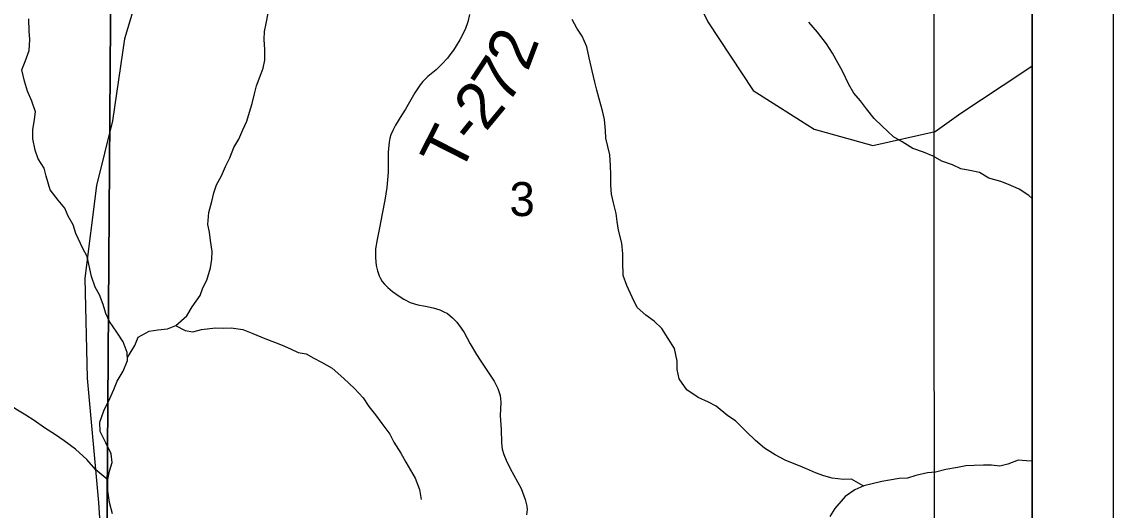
# Model space of a CAD drawing. Extents: x 0 to 34, y 0 to 22.
# Drawn here: x 7.655 to 9, y 17.724 to 18.326 of the extents above; entities that cross this region are included whole.
import ezdxf

# ---------------------------------------------------------------- set-up
doc = ezdxf.new("R2010")
doc.units = 0
for name, color, linetype in [('Default', 7, 'Continuous'), ('GM_X_Minor_River', 7, 'Continuous'), ('GM_X_Rail_Line', 7, 'Continuous'), ('GM_X_Section', 7, 'Continuous'), ('GM_X_Section_Text', 7, 'Continuous'), ('GM_X_Township_Road', 7, 'Continuous'), ('GM_X_Township_Road_Text', 7, 'Continuous'), ('SH_Cut_Line', 7, 'Continuous'), ('SH_Data', 7, 'Continuous')]:
    doc.layers.add(name, color=color, linetype=linetype)

msp = doc.modelspace()

# ---------------------------------------------------------------- linework, layer by layer
at = {"layer": 'Default'}
msp.add_lwpolyline([(8.9, 17.6215), (8.9, 18.6179), (8.8175, 18.6179), (8.7788, 18.6182), (8.7796, 17.6215)], close=True, dxfattribs=at)
at = {"layer": 'GM_X_Minor_River'}
for points in [[(7.7518, 17.8211), (7.7513, 17.8329), (7.7562, 17.8469), (7.7637, 17.8618), (7.7685, 17.8732), (7.7726, 17.8831), (7.7801, 17.8956), (7.7857, 17.9086), (7.7853, 17.9188), (7.7803, 17.9317), (7.7722, 17.9438), (7.7634, 17.957), (7.7588, 17.9668), (7.7557, 17.9778), (7.751, 17.9895), (7.7457, 17.9993), (7.741, 18.0122), (7.7359, 18.0368), (7.7305, 18.0467), (7.7217, 18.0652), (7.7186, 18.0758), (7.7124, 18.0867), (7.7082, 18.0966), (7.7002, 18.1064), (7.6902, 18.1192), (7.6855, 18.1359), (7.6828, 18.1457), (7.6755, 18.1574), (7.6717, 18.1677), (7.6689, 18.182), (7.6688, 18.193), (7.671, 18.2056), (7.6721, 18.2151), (7.6675, 18.2283), (7.6624, 18.2404), (7.6586, 18.2529), (7.6554, 18.2669), (7.6595, 18.2772), (7.6644, 18.2909), (7.6651, 18.3042), (7.6642, 18.3144), (7.6638, 18.3296)], [(7.7856, 17.9123), (7.7947, 17.9272), (7.7988, 17.9375), (7.8121, 17.9448), (7.8227, 17.9464), (7.8349, 17.9476), (7.8451, 17.9518), (7.8587, 17.9637), (7.8654, 17.9747), (7.8752, 17.9888), (7.8782, 17.9983), (7.8834, 18.0078), (7.8879, 18.023), (7.8893, 18.0337), (7.89, 18.0431), (7.8877, 18.0568), (7.8865, 18.067), (7.8845, 18.0765), (7.8859, 18.0913), (7.8893, 18.1046), (7.8918, 18.1152), (7.8952, 18.1251), (7.9012, 18.1361), (7.9061, 18.1476), (7.9117, 18.1586), (7.9165, 18.1711), (7.9225, 18.1814), (7.9278, 18.1928), (7.9326, 18.2035), (7.936, 18.2149), (7.939, 18.2255), (7.9419, 18.2373), (7.9445, 18.2472), (7.949, 18.259), (7.9527, 18.2689), (7.9549, 18.2787), (7.9548, 18.292), (7.954, 18.3041), (7.9543, 18.314), (7.9562, 18.3239), (7.9587, 18.3368)], [(8.6921, 17.7542), (8.6775, 17.7627), (8.6676, 17.7622), (8.6539, 17.7637), (8.6433, 17.7666), (8.6334, 17.7703), (8.6223, 17.7752), (8.6121, 17.7793), (8.5968, 17.7857), (8.5835, 17.7924), (8.5702, 17.8007), (8.5591, 17.8101), (8.548, 17.8214), (8.5346, 17.8346), (8.5251, 17.8406), (8.511, 17.8526), (8.5014, 17.8575), (8.4885, 17.8631), (8.4748, 17.8725), (8.4652, 17.8861), (8.4628, 17.8978), (8.4628, 17.9081), (8.4596, 17.9236), (8.4519, 17.936), (8.4439, 17.9481), (8.4343, 17.9572), (8.424, 17.9647), (8.4133, 17.9741), (8.4072, 17.9866), (8.4006, 18.001), (8.3964, 18.0134), (8.3959, 18.0305), (8.3958, 18.04), (8.3946, 18.0533), (8.3907, 18.0692), (8.3887, 18.0801), (8.3875, 18.09), (8.3844, 18.1029), (8.3817, 18.1135), (8.3812, 18.1249), (8.3811, 18.1381), (8.3807, 18.1487), (8.3798, 18.162), (8.3775, 18.1726), (8.3748, 18.1828), (8.3743, 18.1923), (8.3731, 18.2056), (8.3707, 18.2162), (8.3665, 18.231), (8.3637, 18.2419), (8.3614, 18.2518), (8.3579, 18.2658), (8.3544, 18.2817), (8.3516, 18.2953), (8.3458, 18.3082), (8.3393, 18.3184), (8.3335, 18.329)], [(8.9, 18.1085), (8.8962, 18.1119), (8.884, 18.1198), (8.871, 18.1258), (8.8615, 18.1291), (8.847, 18.1336), (8.8352, 18.1403), (8.8234, 18.1429), (8.8124, 18.1451), (8.8021, 18.15), (8.7888, 18.1544), (8.7781, 18.1604), (8.7663, 18.1653), (8.753, 18.1701), (8.74, 18.178), (8.7294, 18.1844), (8.7152, 18.1976), (8.7057, 18.207), (8.6961, 18.2187), (8.6885, 18.2285), (8.6804, 18.2383), (8.6743, 18.2489), (8.6666, 18.2651), (8.6608, 18.2754), (8.6543, 18.2874), (8.6466, 18.2988), (8.6355, 18.3131), (8.6252, 18.3256)], [(7.8447, 17.9517), (7.8565, 17.9458), (7.866, 17.944), (7.8766, 17.9471), (7.8941, 17.9491), (7.9039, 17.9488), (7.9134, 17.9489), (7.9275, 17.947), (7.9401, 17.9422), (7.9549, 17.9358), (7.9667, 17.9314), (7.9762, 17.9276), (7.9865, 17.9232), (7.996, 17.9187), (8.0055, 17.9168), (8.0151, 17.9116), (8.0246, 17.9067), (8.0375, 17.8992), (8.0521, 17.8864), (8.0651, 17.8744), (8.0758, 17.8627), (8.083, 17.8521), (8.0911, 17.8419), (8.0987, 17.8313), (8.1087, 17.8181), (8.1137, 17.8083), (8.1222, 17.7947), (8.1283, 17.7837), (8.1341, 17.7735), (8.1398, 17.7637), (8.1452, 17.7497), (8.1472, 17.7376)], [(7.7613, 17.7616), (7.7464, 17.7741), (7.7353, 17.7869), (7.7215, 17.7997), (7.7074, 17.8098), (7.6967, 17.817), (7.6834, 17.826), (7.6704, 17.835), (7.6601, 17.8414), (7.6502, 17.8474), (7.638, 17.8553), (7.6266, 17.8639), (7.617, 17.8699), (7.6064, 17.8763), (7.5965, 17.8808), (7.5854, 17.8872), (7.5759, 17.8913), (7.5648, 17.8969), (7.5519, 17.9048), (7.5404, 17.9123), (7.5305, 17.9179), (7.5199, 17.922), (7.5069, 17.9291)], [(7.7669, 17.7199), (7.7634, 17.734), (7.7614, 17.748), (7.7613, 17.762), (7.7635, 17.7723), (7.7665, 17.7829), (7.7652, 17.7939), (7.7587, 17.8075), (7.7518, 17.8211)], [(8.9, 17.7846), (8.8934, 17.7853), (8.8831, 17.786), (8.8702, 17.781), (8.8604, 17.7787), (8.8501, 17.7797), (8.8403, 17.78), (8.8289, 17.7792), (8.8186, 17.7788), (8.808, 17.7768), (8.794, 17.7744), (8.7811, 17.7713), (8.7712, 17.7705), (8.7568, 17.767), (8.7466, 17.7639), (8.7363, 17.7634), (8.7246, 17.7615), (8.7151, 17.7595), (8.703, 17.7568), (8.6927, 17.7544), (8.6817, 17.7494), (8.6696, 17.7414), (8.6572, 17.7265), (8.6508, 17.7166)]]:
    msp.add_lwpolyline(points, dxfattribs=at)
at = {"layer": 'GM_X_Rail_Line'}
msp.add_lwpolyline([(5.9824, 16.6436), (7.149, 16.6283), (7.6814, 16.6224), (7.7376, 16.622), (7.7377, 16.1663), (7.7446, 16.1373), (7.7538, 15.9954), (7.756, 15.9342), (7.7526, 15.9181), (7.7434, 15.892), (7.7355, 15.6105), (7.8392, 15.6096), (8.369, 15.6108), (8.7708, 15.6025), (8.77, 15.1835), (8.767, 14.6265), (8.9, 14.624), (8.9, 20.9)], dxfattribs=at)
at = {"layer": 'GM_X_Section'}
for points in [[(6.7712, 18.6214), (6.7897, 18.6209), (7.7667, 18.6191), (7.7595, 17.6205), (6.7568, 17.6224)], [(7.7667, 18.6191), (7.7955, 18.6195), (8.7788, 18.6182), (8.7796, 17.6215), (7.7595, 17.6205)]]:
    msp.add_lwpolyline(points, close=True, dxfattribs=at)
at = {"layer": 'GM_X_Township_Road'}
for points in [[(7.8117, 18.4807), (7.8122, 18.4788), (7.8194, 18.4479), (7.8179, 18.4023), (7.7996, 18.3642), (7.7818, 18.3052), (7.7671, 18.2041), (7.7472, 18.1242), (7.7329, 18.0102), (7.7357, 17.8869), (7.7498, 17.734), (7.755, 17.6517), (7.7598, 17.5188), (7.7622, 17.4448)], [(8.4568, 18.4172), (8.5007, 18.326), (8.5563, 18.2414), (8.6314, 18.1938), (8.704, 18.1738), (8.7805, 18.1908), (8.8121, 18.2134), (8.89, 18.2647), (8.9, 18.2719)], [(8.2071, 18.335), (8.2048, 18.3259), (8.2017, 18.3165), (8.1951, 18.304), (8.1905, 18.2964), (8.1871, 18.2912), (8.184, 18.2868), (8.1798, 18.2813), (8.1728, 18.2737), (8.1658, 18.267), (8.1557, 18.2585), (8.1495, 18.2523), (8.1462, 18.2485), (8.1397, 18.2385), (8.128, 18.2185), (8.1234, 18.2115), (8.1156, 18.1987), (8.1123, 18.1921), (8.11, 18.1866), (8.1086, 18.1826), (8.1078, 18.1777), (8.1068, 18.1658), (8.1069, 18.1517), (8.1065, 18.141), (8.1051, 18.122), (8.1028, 18.1063), (8.0994, 18.0896), (8.0961, 18.0723), (8.0933, 18.0577), (8.0913, 18.0465), (8.091, 18.0352), (8.092, 18.0259), (8.0934, 18.0191), (8.0955, 18.0131), (8.0971, 18.0098), (8.0994, 18.0062), (8.1022, 18.0027), (8.1064, 17.9988), (8.1122, 17.9938), (8.1191, 17.9887), (8.126, 17.9843), (8.134, 17.9804), (8.1432, 17.9775), (8.1527, 17.9757), (8.1623, 17.9736), (8.1705, 17.971), (8.1746, 17.9693), (8.1798, 17.9665), (8.186, 17.9615), (8.1914, 17.9558), (8.1966, 17.9487), (8.2004, 17.9432), (8.2079, 17.9295), (8.2154, 17.916), (8.2199, 17.9093), (8.2317, 17.8919), (8.2374, 17.8831), (8.2419, 17.8741), (8.2445, 17.8658), (8.2455, 17.8574), (8.2449, 17.8406), (8.2459, 17.8239), (8.2462, 17.8072), (8.2472, 17.7994), (8.2491, 17.7929), (8.2522, 17.786), (8.2571, 17.7759), (8.2707, 17.7512), (8.2756, 17.7376), (8.2775, 17.7293), (8.2778, 17.7251), (8.277, 17.7187)]]:
    msp.add_lwpolyline(points, dxfattribs=at)
at = {"layer": 'SH_Cut_Line'}
msp.add_lwpolyline([(5.9824, 16.6436), (7.149, 16.6283), (7.6814, 16.6224), (7.7376, 16.622), (7.7377, 16.1663), (7.7446, 16.1373), (7.7538, 15.9954), (7.756, 15.9342), (7.7526, 15.9181), (7.7434, 15.892), (7.7355, 15.6105), (7.8392, 15.6096), (8.369, 15.6108), (8.7708, 15.6025), (8.77, 15.1835), (8.767, 14.6265), (8.9, 14.624), (8.9, 20.9)], dxfattribs=at)
at = {"layer": 'SH_Data'}
for p, q in [((9, 21), (9, 14)), ((8.9, 20.9), (8.9, 14.1))]:
    msp.add_line(p, q, dxfattribs=at)

# ---------------------------------------------------------------- texts
at = {"layer": 'GM_X_Section_Text'}
msp.add_text('3', height=0.0419, rotation=0, dxfattribs=at).set_placement((8.2562, 18.0867))
at = {"layer": 'GM_X_Township_Road_Text'}
for s, rotation, p in [('2', 69.4488, (8.2787, 18.2637)), ('7', 56.721, (8.2533, 18.2222)), ('2', 50.3876, (8.2269, 18.1898)), ('T', 63.0689, (8.1948, 18.1365)), ('-', 51.05, (8.2124, 18.1718))]:
    msp.add_text(s, height=0.0568, rotation=rotation, dxfattribs=at).set_placement(p)

doc.saveas('drawing.dxf')
